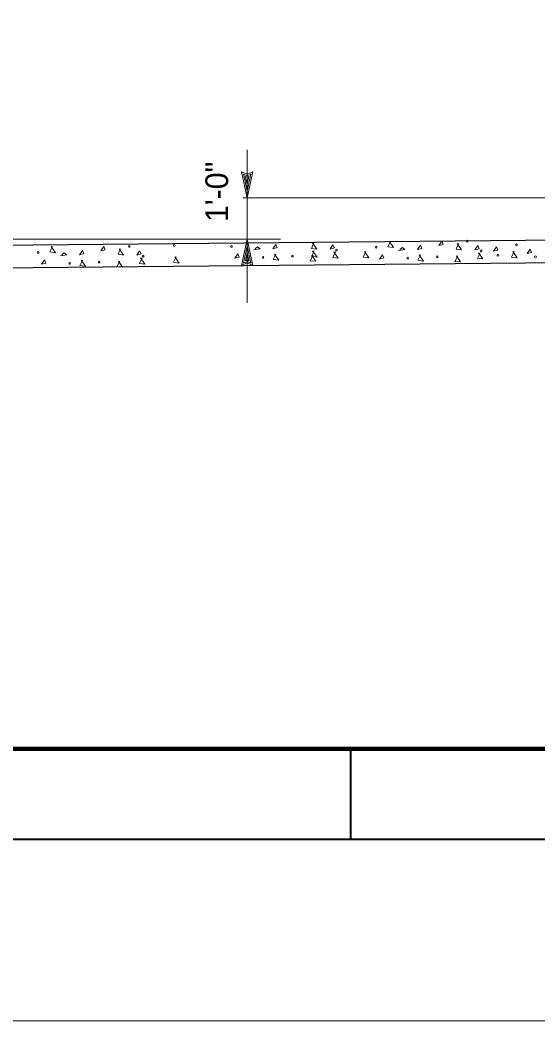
# Model space of a CAD drawing. Extents: x -22.3 to 19.7, y -11.8 to 18.2.
# Drawn here: x -7.13 to -4.28, y -11.84 to -6.32 of the extents above; entities that cross this region are included whole.
import ezdxf

# ---------------------------------------------------------------- set-up
doc = ezdxf.new("R2010")
doc.units = 0
doc.header["$LTSCALE"] = 0.05
doc.layers.add('1', color=7, linetype='Continuous', lineweight=13)
doc.layers.add('2', color=7, linetype='Continuous', lineweight=13)

msp = doc.modelspace()

# ---------------------------------------------------------------- linework, layer by layer
at = {"layer": '1'}
for p, q in [((-5.87842, -7.30469), (-5.90942, -7.16069)), ((-5.87842, -7.30469), (-5.84742, -7.16069)), ((-5.87842, -7.26769), (-5.89842, -7.17369)), ((-5.89842, -7.17369), (-5.87842, -7.18269)), ((-5.87842, -7.23169), (-5.88842, -7.18669)), ((-5.88842, -7.18669), (-5.87842, -7.19069)), ((-5.87842, -7.26769), (-5.85842, -7.17369)), ((-5.87842, -7.18269), (-5.85842, -7.17369)), ((-5.87842, -7.23169), (-5.86942, -7.18669)), ((-5.87842, -7.19069), (-5.86942, -7.18669)), ((-3.82742, -7.30469), (-5.89942, -7.30469)), ((-5.69442, -7.53269), (-18.28242, -7.53269)), ((-5.87842, -7.53269), (-5.90942, -7.67669)), ((-5.87842, -7.53269), (-5.84742, -7.67669)), ((-5.87842, -7.56969), (-5.89842, -7.66369)), ((-5.87842, -7.60569), (-5.88742, -7.65069)), ((-5.87842, -7.56969), (-5.85842, -7.66369)), ((-5.87842, -7.60569), (-5.86842, -7.65069)), ((-5.87842, -7.65469), (-5.89842, -7.66369)), ((-5.87842, -7.64669), (-5.88742, -7.65069)), ((-5.86842, -7.65069), (-5.87842, -7.64669)), ((-5.85842, -7.66369), (-5.87842, -7.65469)), ((19.69058, -11.83969), (-22.30942, -11.83969))]:
    msp.add_line(p, q, dxfattribs=at)
at = {"layer": '1', "lineweight": 25}
for p, q in [((-10.87842, -7.59969), (-3.99142, -7.53369)), ((-10.88242, -7.72469), (-3.99142, -7.65869))]:
    msp.add_line(p, q, dxfattribs=at)
at = {"layer": '1', "lineweight": 40}
msp.add_line((-5.30942, -10.33969), (-5.30942, -10.83969), dxfattribs=at)
msp.add_lwpolyline([(-21.30942, -10.83969), (-21.30942, 17.16031), (18.69058, 17.16031), (18.69058, -10.83969)], close=True, dxfattribs=at)
at = {"layer": '1', "lineweight": 90}
msp.add_lwpolyline([(-19.80942, 16.66031), (18.19058, 16.66031), (18.19058, -10.33969), (-19.80942, -10.33969)], close=True, dxfattribs=at)
at = {"layer": '1'}
for points in [[(-5.87842, -7.88369), (-5.87842, -7.53269), (-5.87842, -7.30469), (-5.87842, -7.04069)], [(-5.90942, -7.16069), (-5.87842, -7.17469), (-5.84742, -7.16069)], [(-5.84742, -7.67669), (-5.87842, -7.66269), (-5.90942, -7.67669)]]:
    msp.add_lwpolyline(points, dxfattribs=at)
at = {"layer": '2'}
for points in [[(-5.51042, -7.55269), (-5.52442, -7.58269), (-5.49442, -7.58669), (-5.51842, -7.55269)], [(-5.08842, -7.54369), (-5.10242, -7.57369), (-5.07242, -7.57769), (-5.09642, -7.54369)], [(-6.95042, -7.57269), (-6.96442, -7.60269), (-6.93442, -7.60669), (-6.95842, -7.57269)], [(-6.89942, -7.61769), (-6.88542, -7.60769), (-6.87142, -7.61769), (-6.90742, -7.62369)], [(-6.57542, -7.58569), (-6.58942, -7.61569), (-6.55942, -7.61969), (-6.58342, -7.58569)], [(-5.83442, -7.58469), (-5.82042, -7.57469), (-5.80642, -7.58469), (-5.84242, -7.59069)], [(-5.50942, -7.59669), (-5.52342, -7.62669), (-5.49342, -7.63069), (-5.51742, -7.59669)], [(-5.39242, -7.60269), (-5.40642, -7.63269), (-5.37642, -7.63669), (-5.40042, -7.60269)], [(-5.22442, -7.60069), (-5.23842, -7.63069), (-5.20842, -7.63469), (-5.23242, -7.60069)], [(-5.03742, -7.58869), (-5.02342, -7.57869), (-5.00942, -7.58869), (-5.04542, -7.59469)], [(-4.71342, -7.55669), (-4.72742, -7.58669), (-4.69742, -7.59069), (-4.72142, -7.55669)], [(-4.59542, -7.60669), (-4.60942, -7.63669), (-4.57942, -7.64069), (-4.60342, -7.60669)], [(-4.40742, -7.60069), (-4.42142, -7.63069), (-4.39142, -7.63469), (-4.41542, -7.60069)], [(-6.78542, -7.64769), (-6.79942, -7.67769), (-6.76942, -7.68169), (-6.79342, -7.64769)], [(-6.57942, -7.65369), (-6.59542, -7.68369), (-6.56542, -7.68569), (-6.58742, -7.65369)], [(-6.45742, -7.63569), (-6.47142, -7.66569), (-6.44142, -7.66969), (-6.46542, -7.63569)], [(-6.26942, -7.62969), (-6.28342, -7.65969), (-6.25342, -7.66369), (-6.27742, -7.62969)], [(-5.72042, -7.61469), (-5.73442, -7.64469), (-5.70442, -7.64869), (-5.72842, -7.61469)], [(-5.51442, -7.62069), (-5.53042, -7.65069), (-5.50042, -7.65269), (-5.52242, -7.62069)], [(-4.92342, -7.61869), (-4.93742, -7.64869), (-4.90742, -7.65269), (-4.93142, -7.61869)], [(-4.71742, -7.62469), (-4.73342, -7.65469), (-4.70342, -7.65669), (-4.72542, -7.62469)]]:
    msp.add_lwpolyline(points, dxfattribs=at)
for points in [[(-4.82242, -7.56769), (-4.80642, -7.54369), (-4.79842, -7.56169)], [(-6.80142, -7.61769), (-6.78542, -7.59369), (-6.77742, -7.61169)], [(-6.68442, -7.59669), (-6.66842, -7.57269), (-6.66042, -7.59069)], [(-6.48642, -7.61969), (-6.47042, -7.59569), (-6.46242, -7.61369)], [(-5.73642, -7.58469), (-5.72042, -7.56069), (-5.71242, -7.57869)], [(-5.42142, -7.58669), (-5.40542, -7.56269), (-5.39742, -7.58069)], [(-4.93942, -7.58869), (-4.92342, -7.56469), (-4.91542, -7.58269)], [(-4.62442, -7.59069), (-4.60842, -7.56669), (-4.60042, -7.58469)], [(-4.52142, -7.59869), (-4.50542, -7.57469), (-4.49742, -7.59269)], [(-4.33542, -7.61069), (-4.31942, -7.58669), (-4.31142, -7.60469)], [(-7.01142, -7.67069), (-6.99542, -7.64669), (-6.98742, -7.66469)], [(-5.94642, -7.63769), (-5.93042, -7.61369), (-5.92242, -7.63169)], [(-5.14942, -7.64169), (-5.13342, -7.61769), (-5.12542, -7.63569)]]:
    msp.add_lwpolyline(points, close=True, dxfattribs=at)
for centre in [(-4.66542, -7.54306), (-7.02992, -7.60506), (-6.52742, -7.57206), (-6.27992, -7.56681), (-5.96492, -7.57206), (-5.38667, -7.59231), (-5.16792, -7.57606), (-4.58967, -7.59631), (-4.39392, -7.56331), (-6.85592, -7.66581), (-6.69392, -7.65831), (-6.45167, -7.62531), (-5.79092, -7.63281), (-5.62892, -7.62531), (-4.99392, -7.63681), (-4.83192, -7.62931), (-4.49692, -7.62031), (-4.28992, -7.62931)]:
    msp.add_circle(centre, 0.00487, dxfattribs=at)

# ---------------------------------------------------------------- texts
at = {"layer": '1'}
msp.add_text('1\'-0"', height=0.125, rotation=90, dxfattribs=at).set_placement((-5.98342, -7.43769))

doc.saveas('drawing.dxf')
